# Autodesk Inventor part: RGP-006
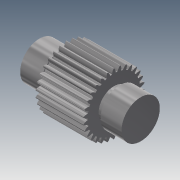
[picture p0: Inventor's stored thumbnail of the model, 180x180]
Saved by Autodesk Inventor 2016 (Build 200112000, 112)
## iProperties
Created: 2013-09
Part Number: RGP-006
Material: Stainless Steel
Document SubType Name: Modeling
Designer: normanpa
Density: 8.08 g/cm^3
Appearance: Semi-Polished
Description: DRIVEN SHAFT GEAR
Mass: 1639.46 g
Surface Area: 329.783 cm^2
Volume: 202.904 cm^3
CustomPartVersion: 1
Author: Autodesk
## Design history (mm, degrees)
sketch "Main Sketch"
  geometry: L1 (0, 0)-(106, 0) reference; L2 (0, 0)-(0, 20); L3 (22, 20)-(22, 16); L4 (0, 20)-(22, 20); L5 (22, 16)-(28, 16); L6 (28, 16)-(28, 32.055); L7 (78, 32.055)-(78, 16); L8 (28, 32.055)-(78, 32.055); L9 (78, 16)-(84, 16); L10 (84, 16)-(84, 20); L11 (106, 20)-(106, 0); L12 (84, 20)-(106, 20)
  constraints: 24 end point, 6 vertical, 4 horizontal
  dimensions: "d3" = 40 diameter of L4 L1 (derived); "d4" = 32 diameter of L5 L1 (derived); "d5" = 64.11 diameter of L8 L1 (derived); "d6" = 32 diameter of L9 L1 (derived); "d7" = 40 diameter of L12 L1 (derived)
revolve "Revolution1" sketch "Main Sketch" stored, may be unused: angle "d8" = 0 deg
sketch "Sketch3"
  geometry: 1 further point
sketch "Sketch4"
  geometry: A1 r 32.055 centre (0, 0) between (-3, 31.914) and (3, 31.914) reference; A2 r 27.5 centre (0, 0) between (-1, 27.482) and (1, 27.482); A3 r 7.5 centre (-8.467, 26.78) between (-1, 27.482) and (-3, 31.914); A4 r 7.5 centre (8.467, 26.78) between (3, 31.914) and (1, 27.482); 1 further point
  constraints: 8 point on circle, 3 centre point, 1 coincident, 1 equal radius
  dimensions: "d9" = 55 diameter of A2; "d10" = 3 horizontal distance of A1.start point (0, 0); "d11" = 3 horizontal distance of A1.end point (0, 0) (= d10); "d12" = 1 horizontal distance of A2.start point (0, 0); "d13" = 1 horizontal distance of A2.end point (0, 0) (= d12); "d14" = 7.5 radius of A3
extrude "Extrusion1" cut sketch "Sketch4" stored distance "d15" = 10; taper "d16" = 0 deg
body "Solid1"
pattern_circular "Circular Pattern1" dims angle "d18" = 360 deg
other parameters: "d0" = 0, "d1" = 0, "d2" = 0
